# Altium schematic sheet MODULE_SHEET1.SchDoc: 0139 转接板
size 1188 x 840 mm; REV: 1.0; DESIGNER: LouKangHua
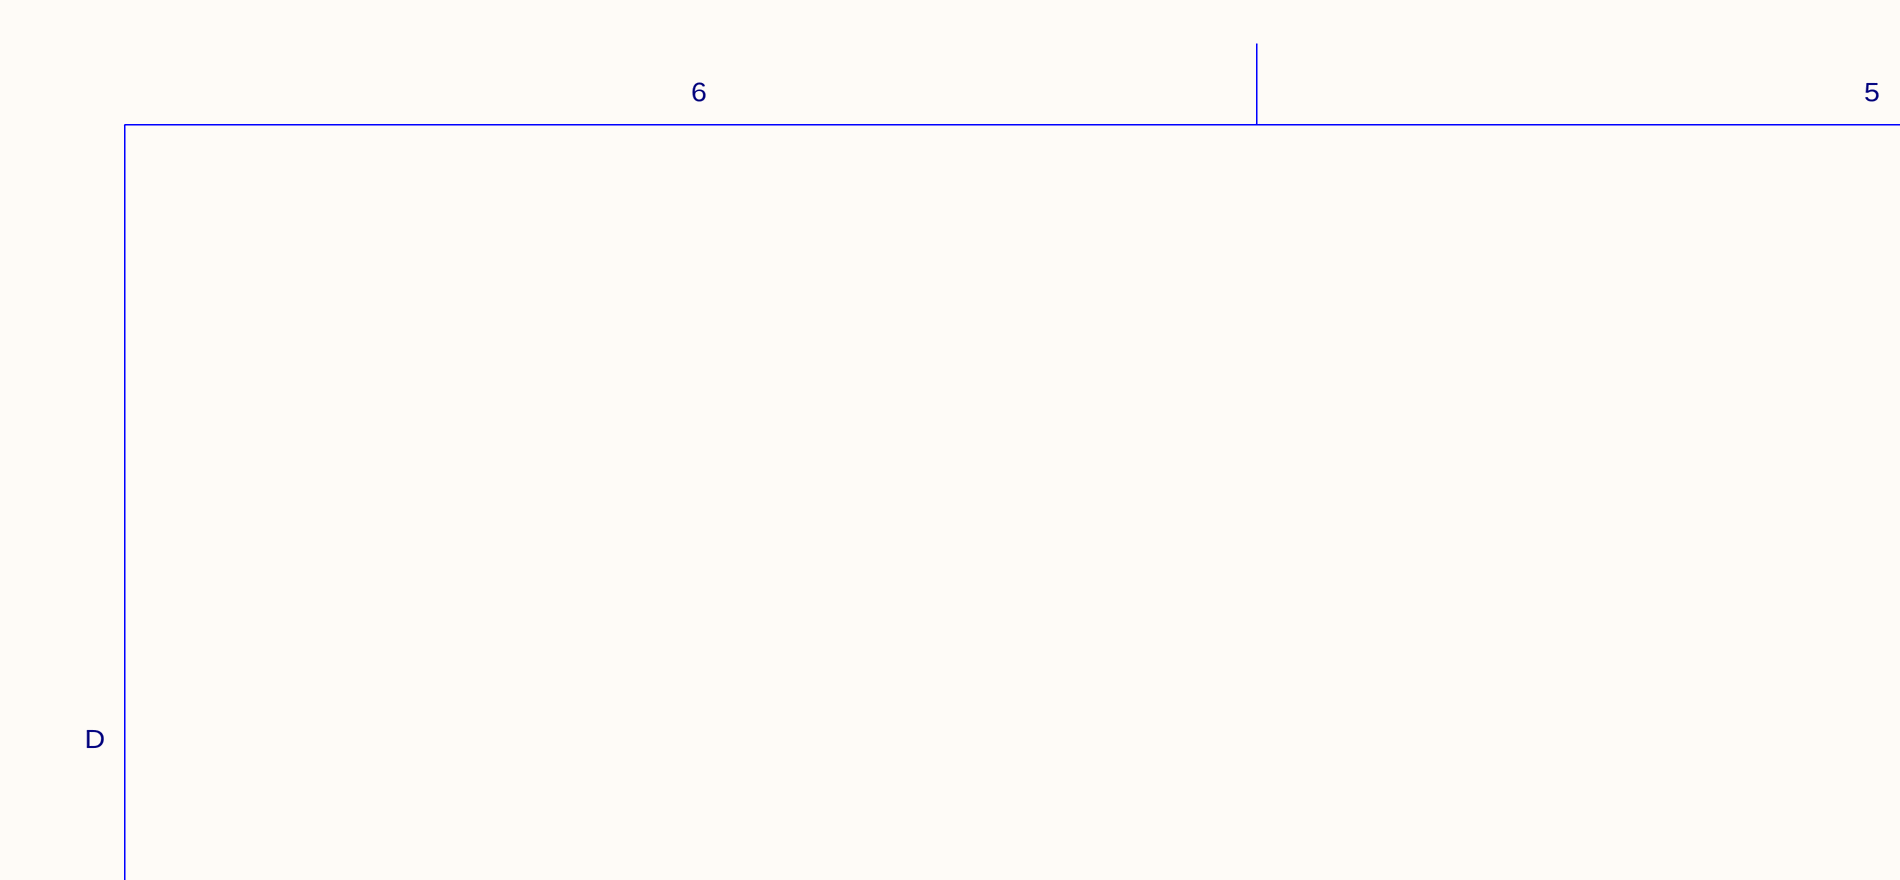
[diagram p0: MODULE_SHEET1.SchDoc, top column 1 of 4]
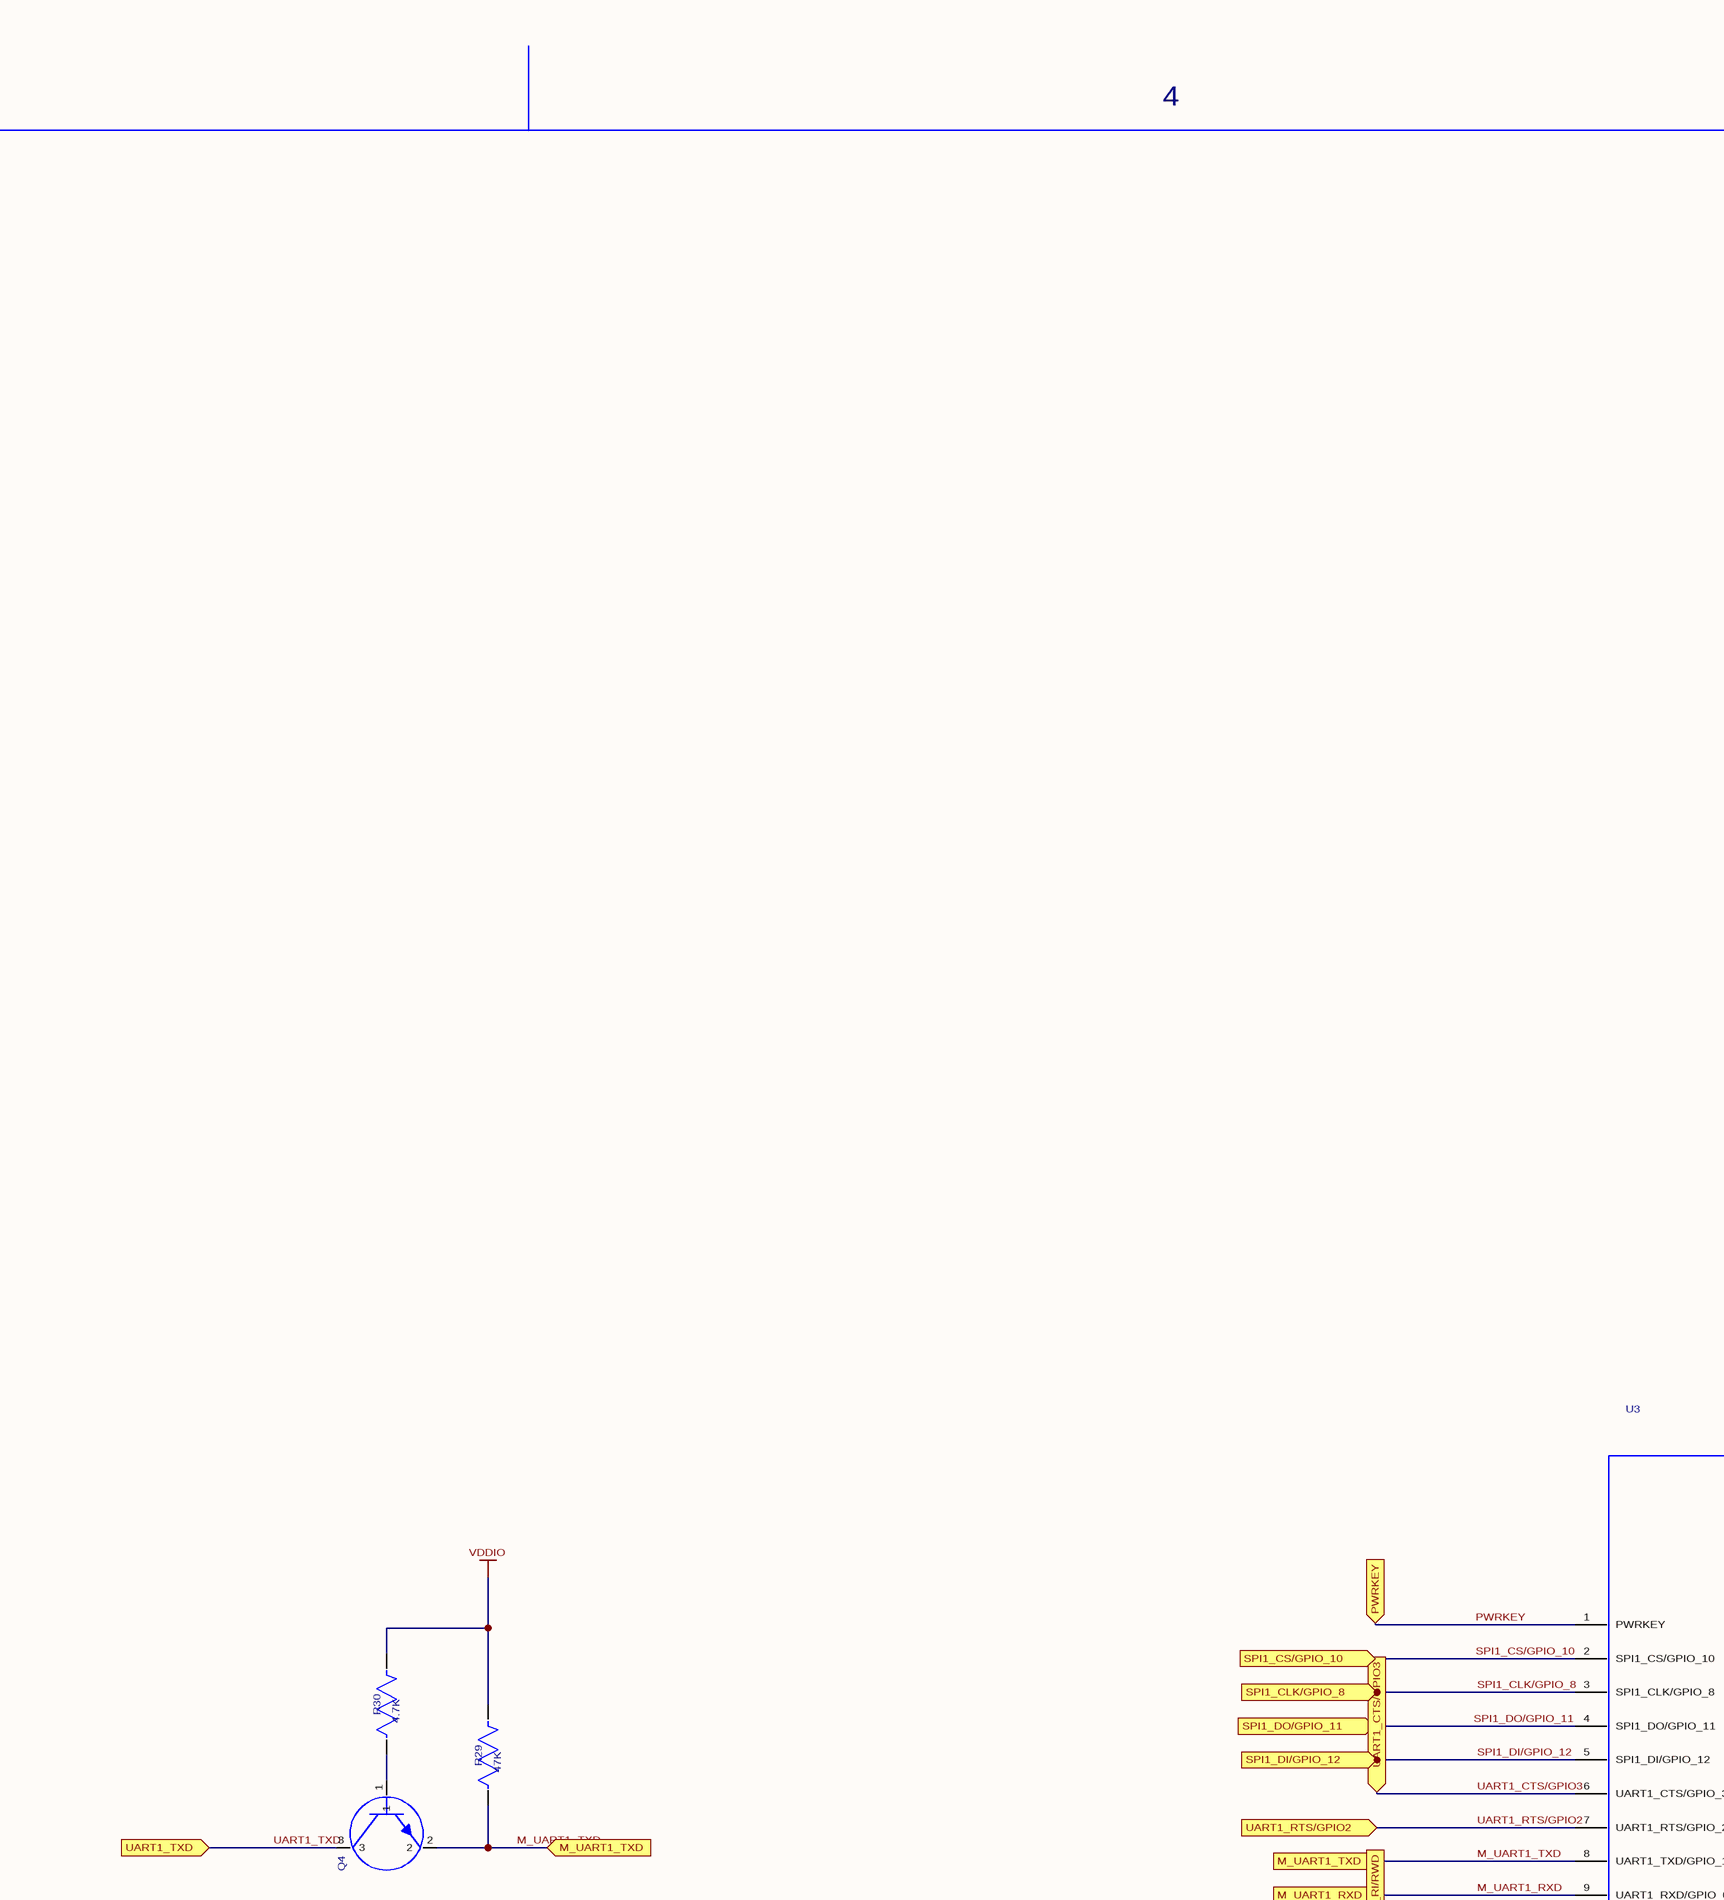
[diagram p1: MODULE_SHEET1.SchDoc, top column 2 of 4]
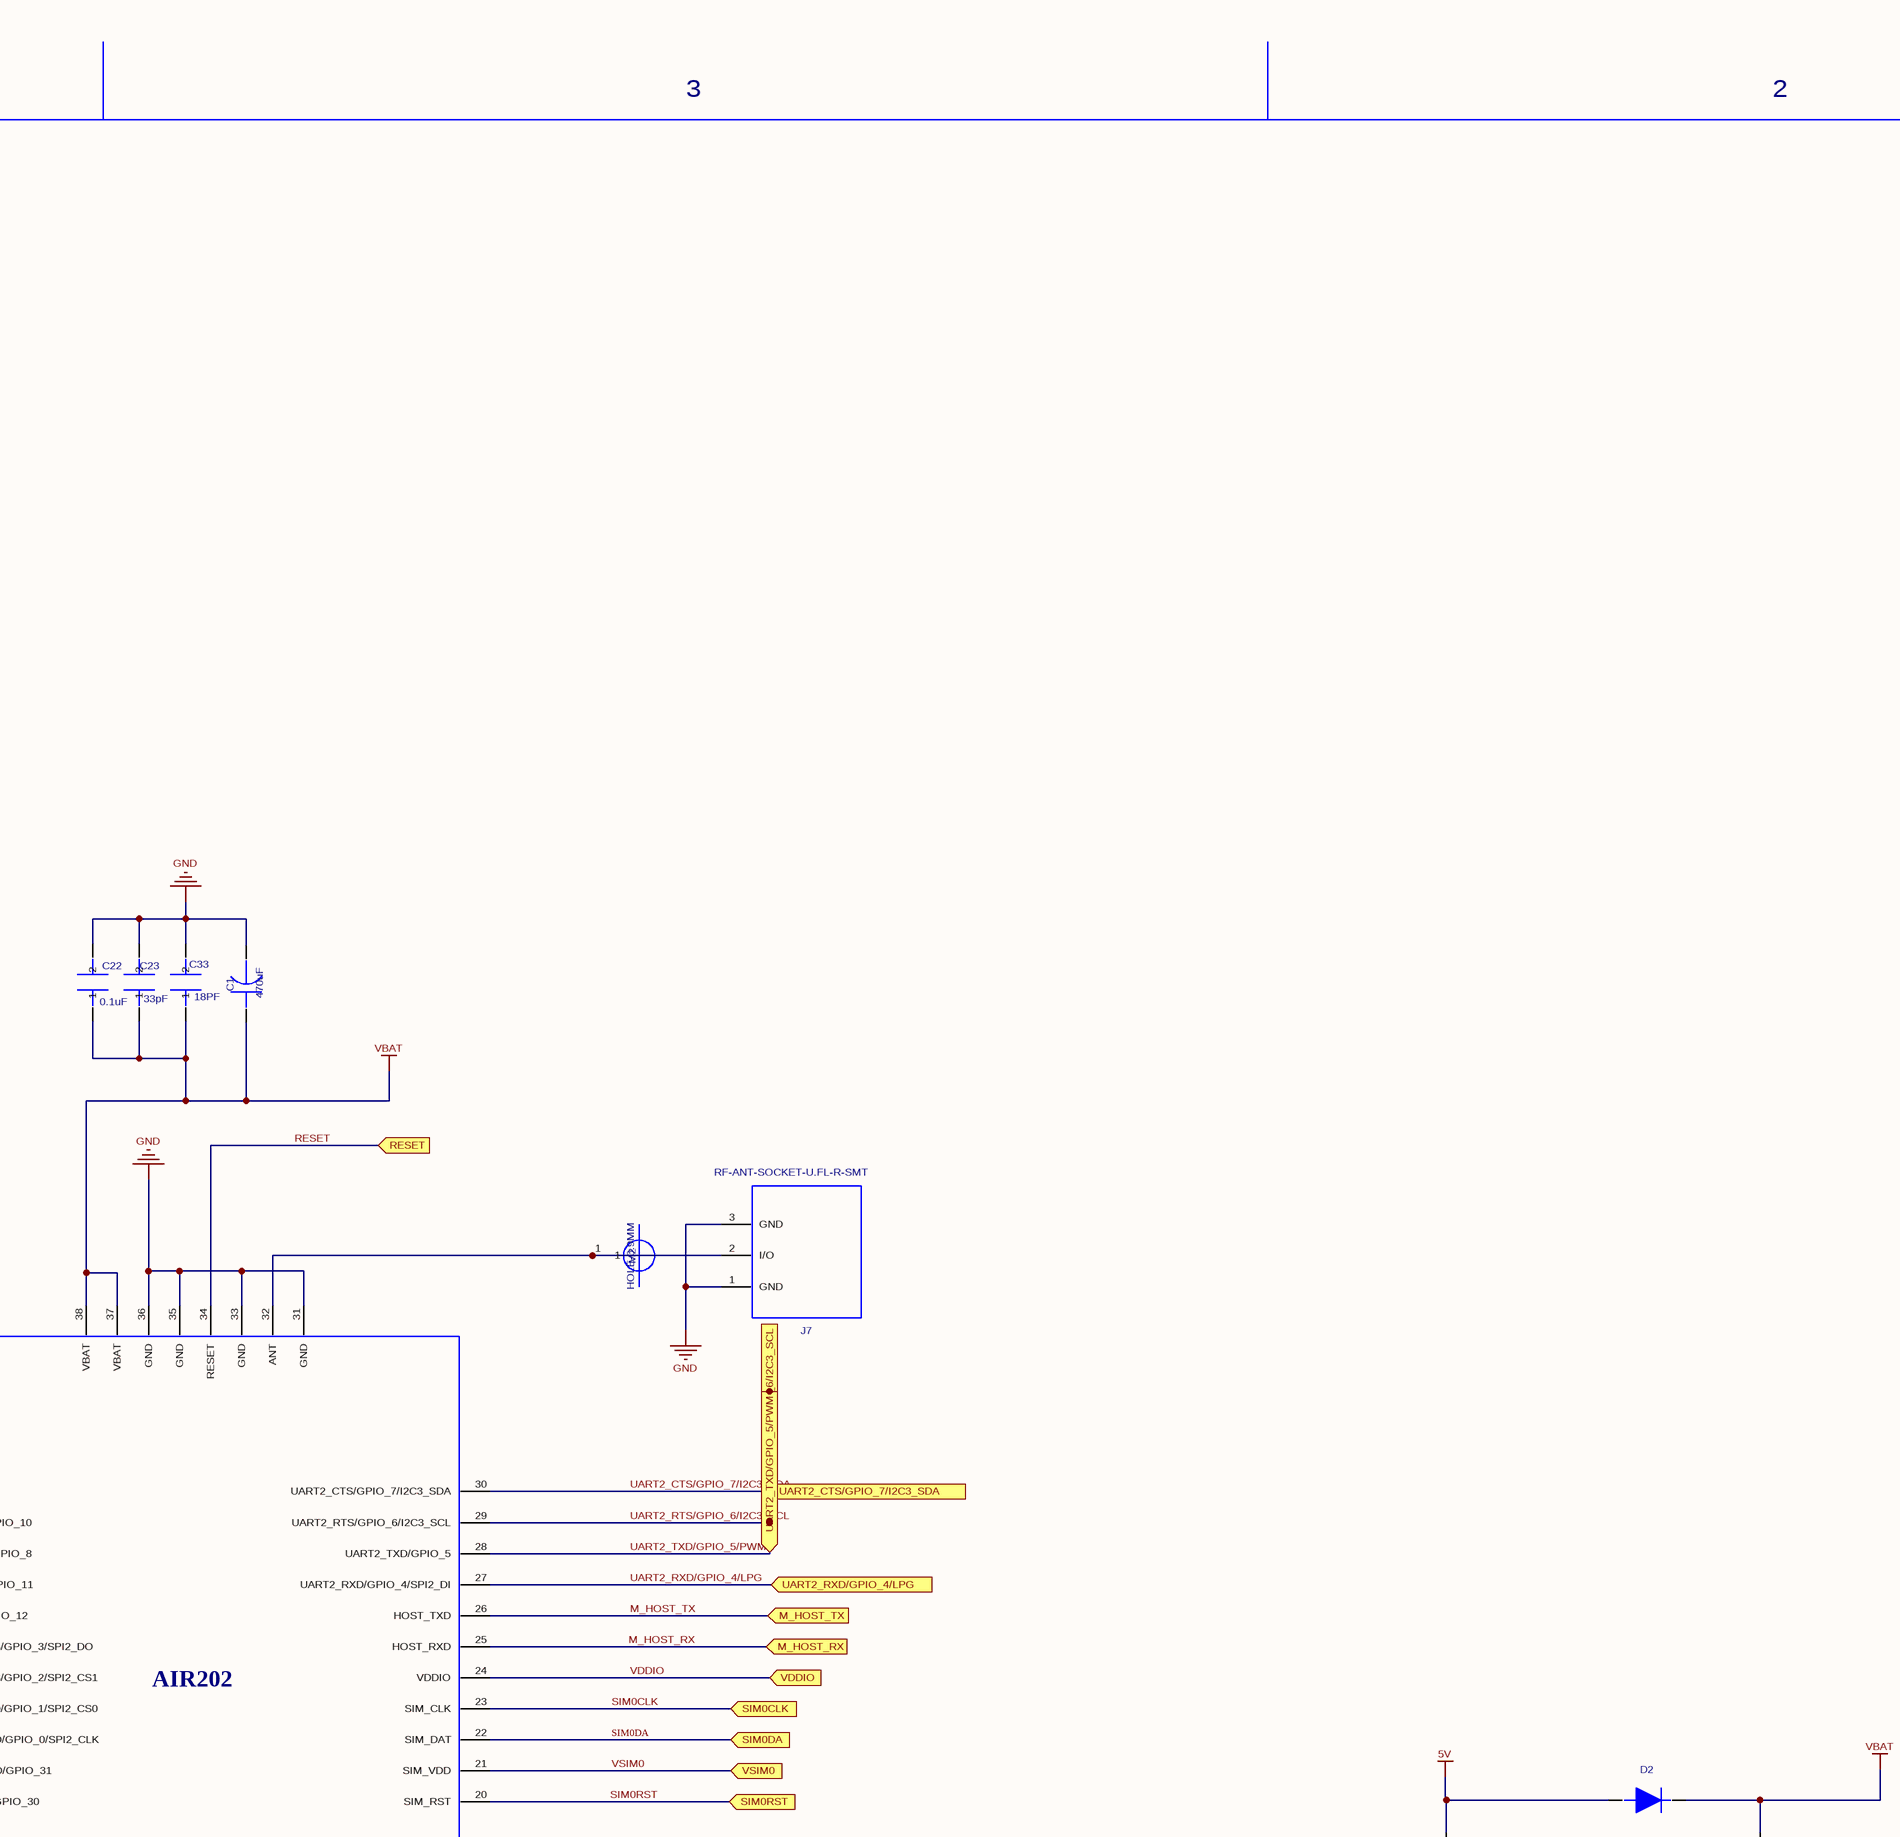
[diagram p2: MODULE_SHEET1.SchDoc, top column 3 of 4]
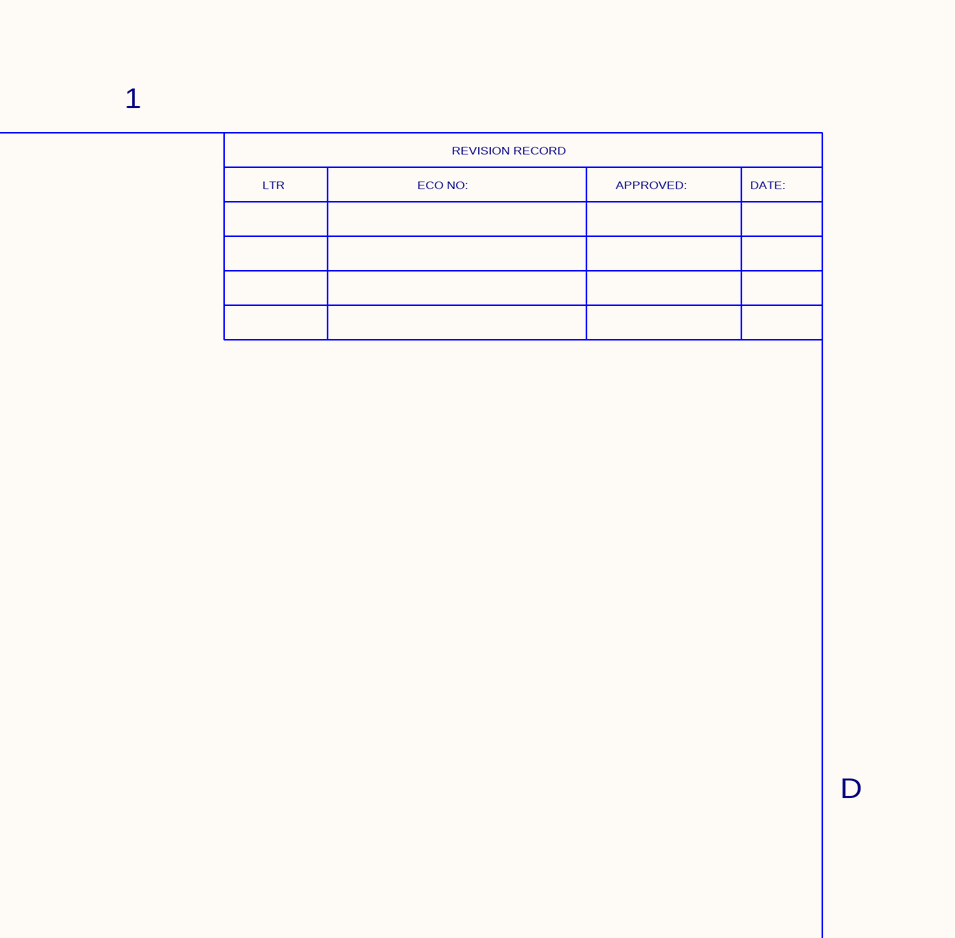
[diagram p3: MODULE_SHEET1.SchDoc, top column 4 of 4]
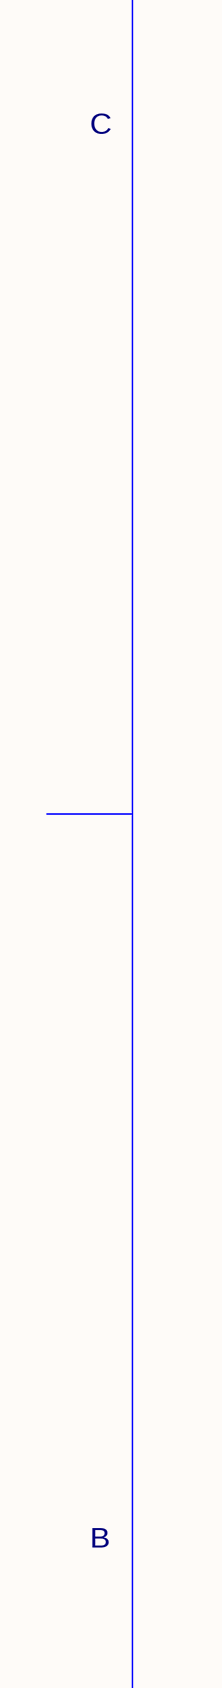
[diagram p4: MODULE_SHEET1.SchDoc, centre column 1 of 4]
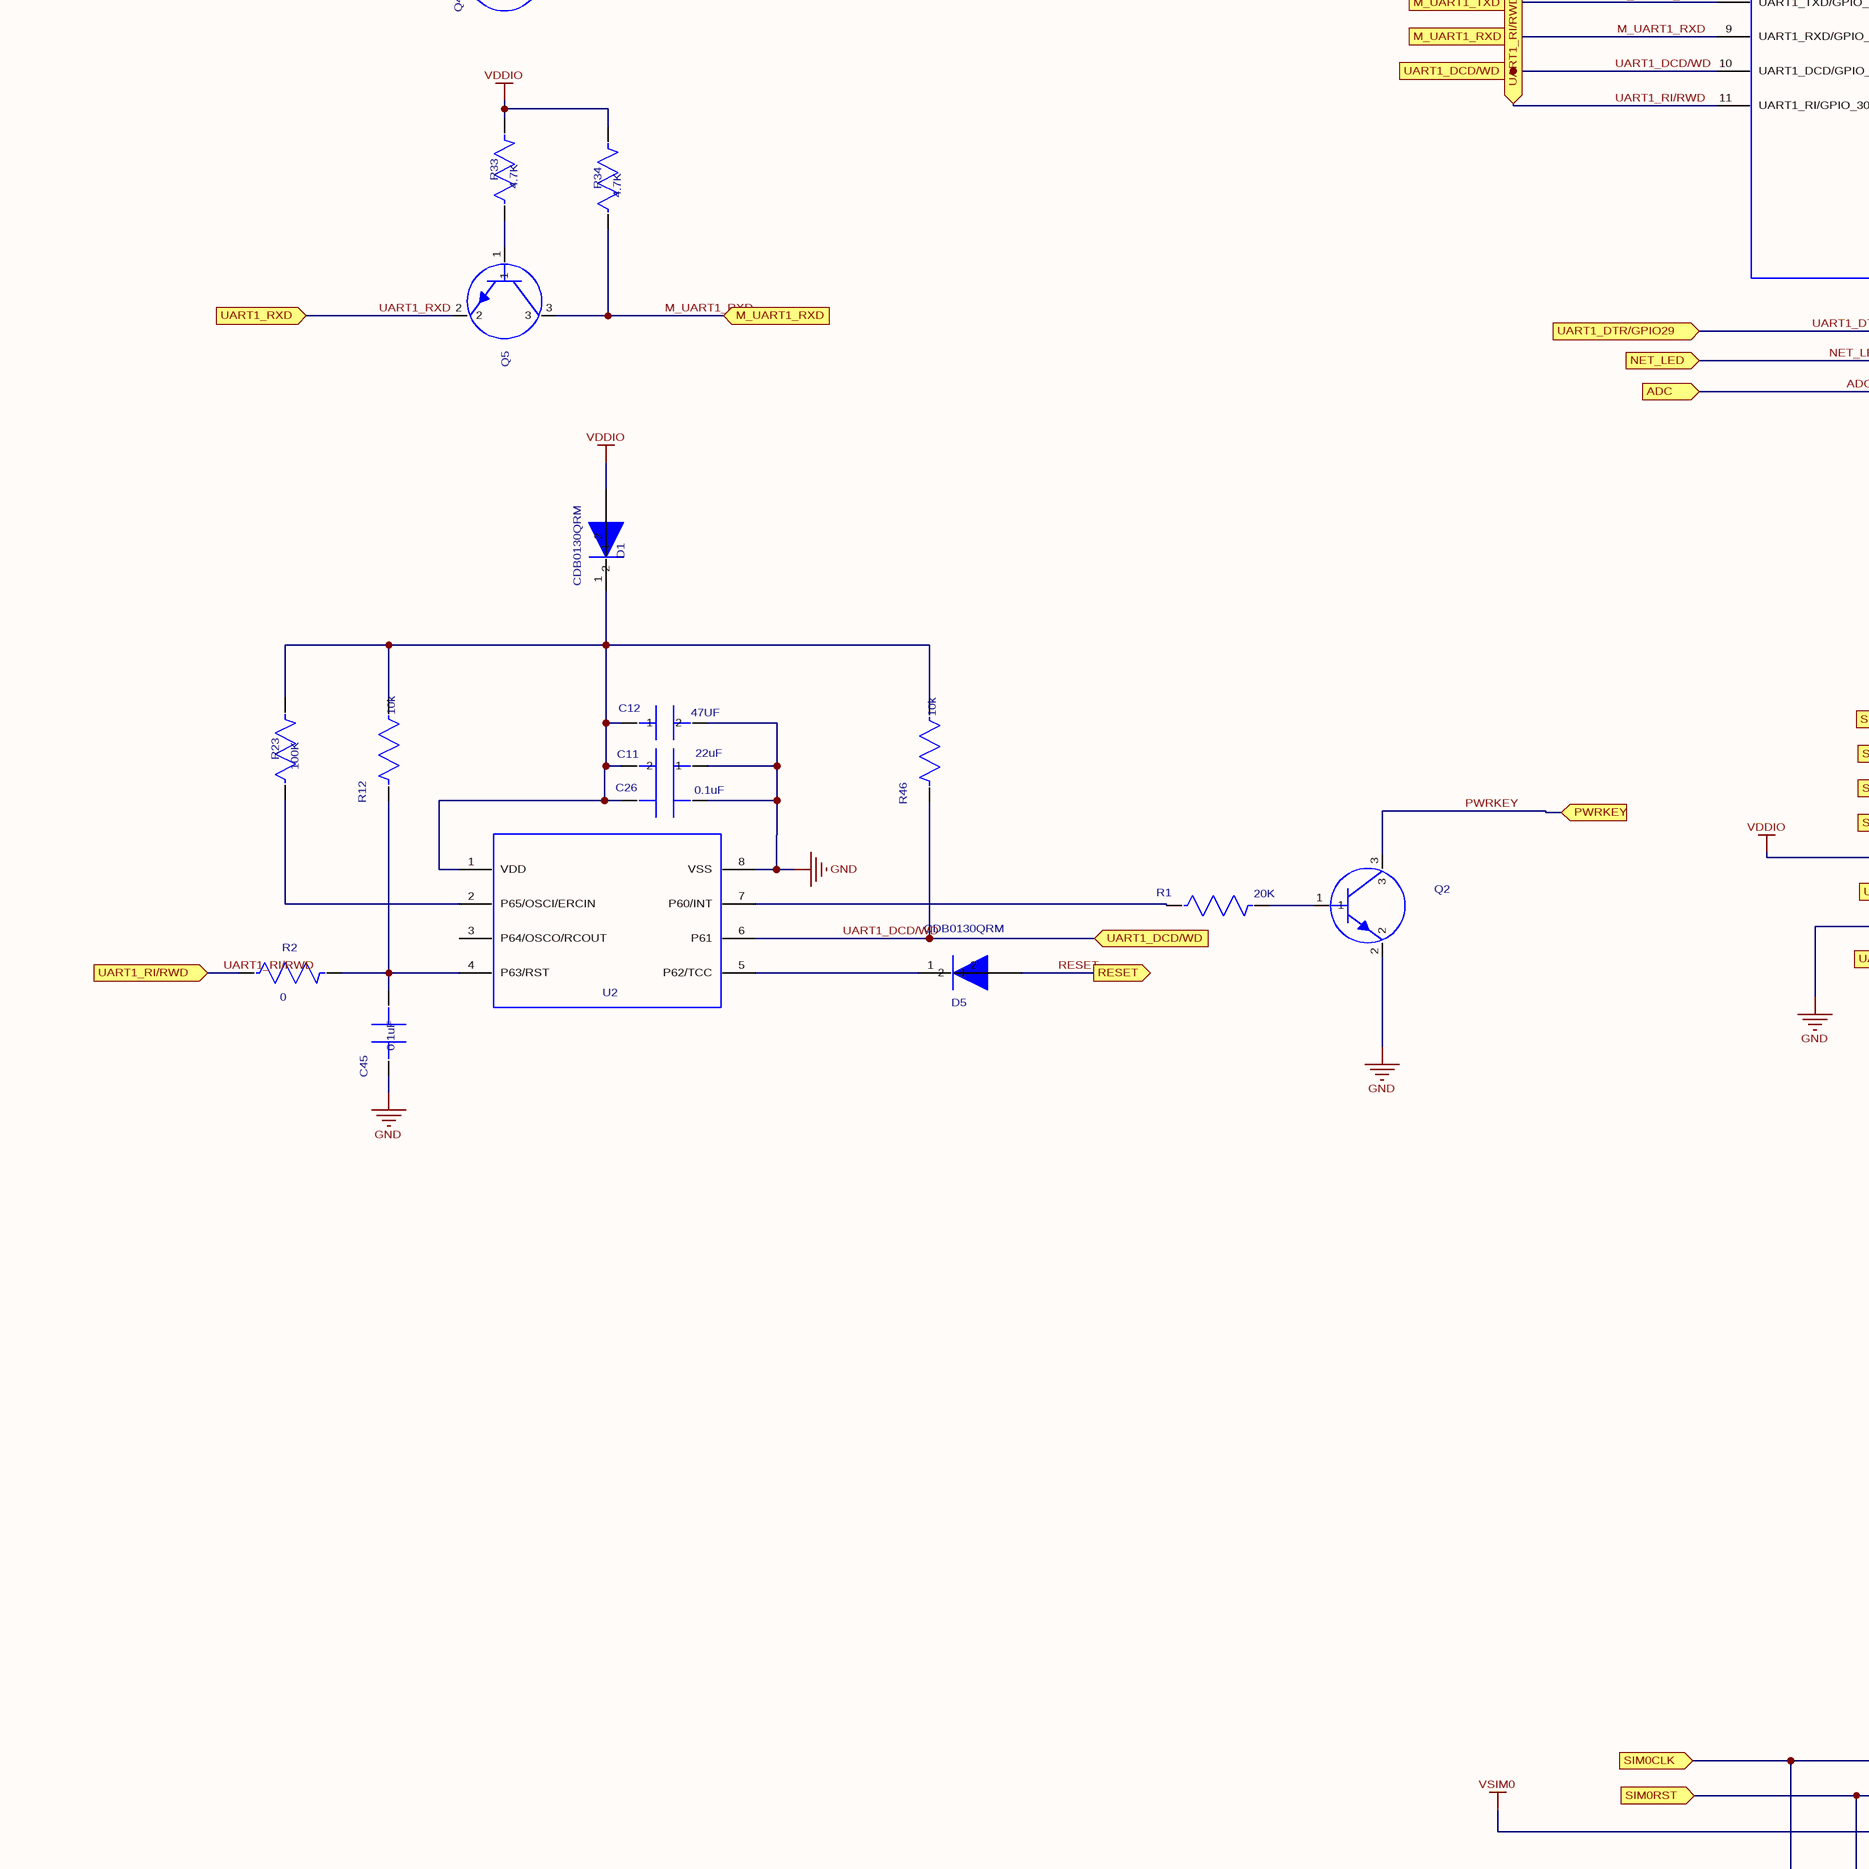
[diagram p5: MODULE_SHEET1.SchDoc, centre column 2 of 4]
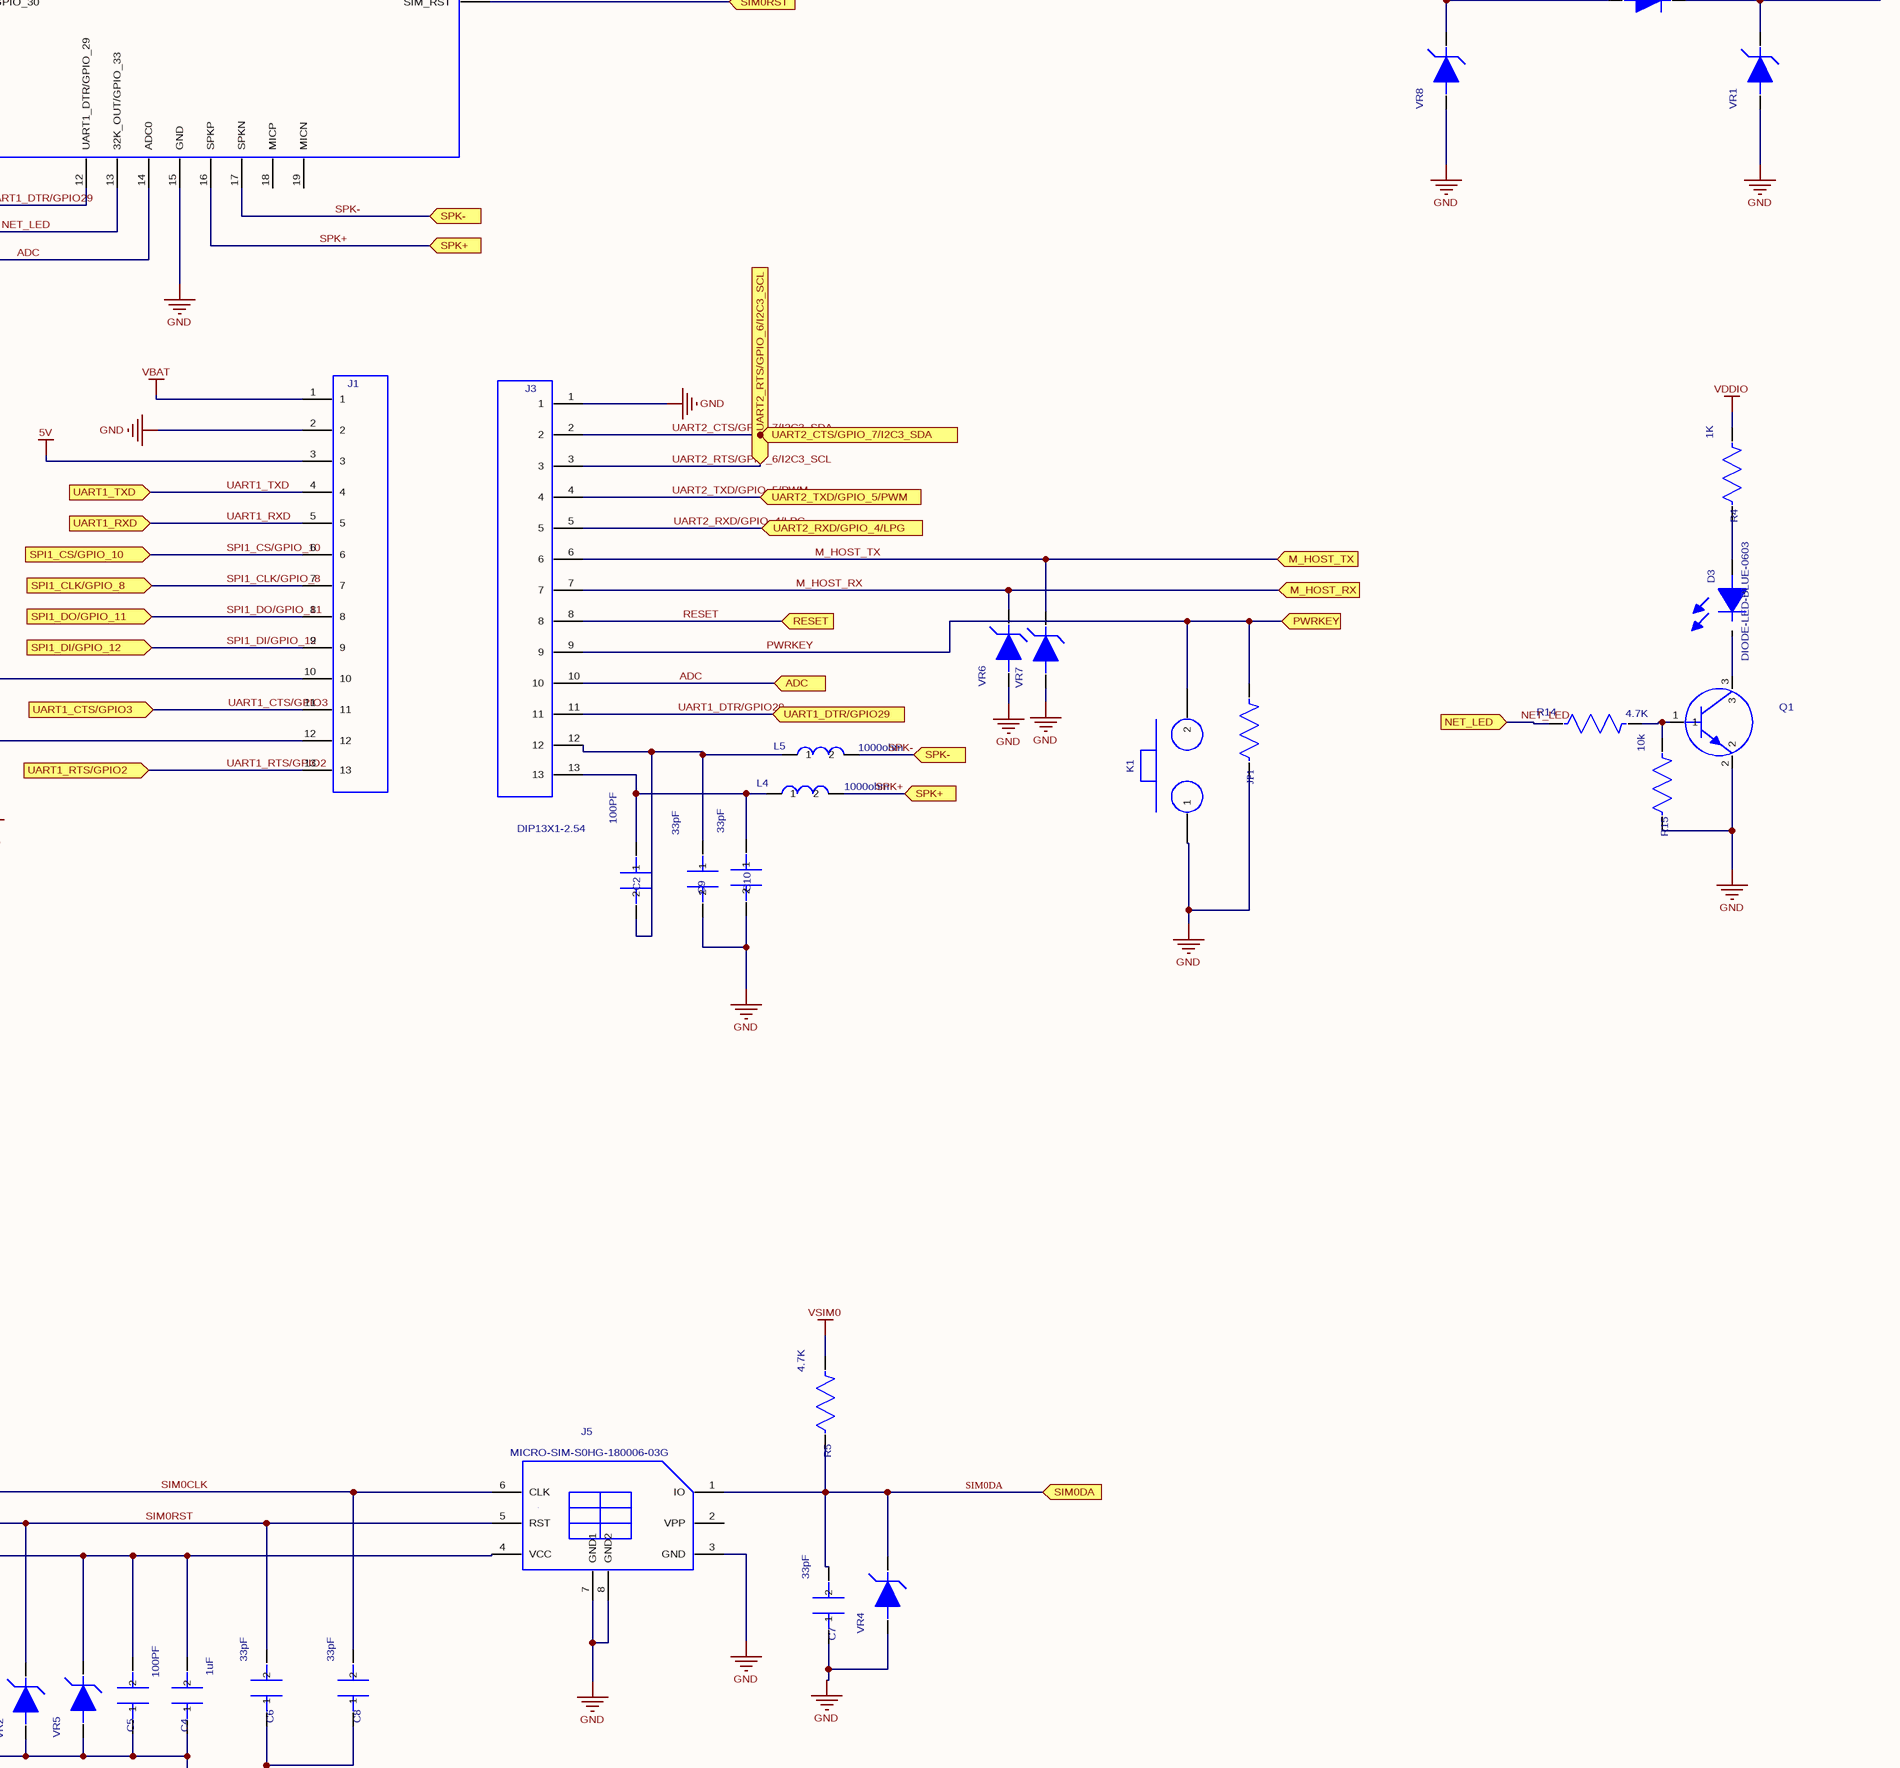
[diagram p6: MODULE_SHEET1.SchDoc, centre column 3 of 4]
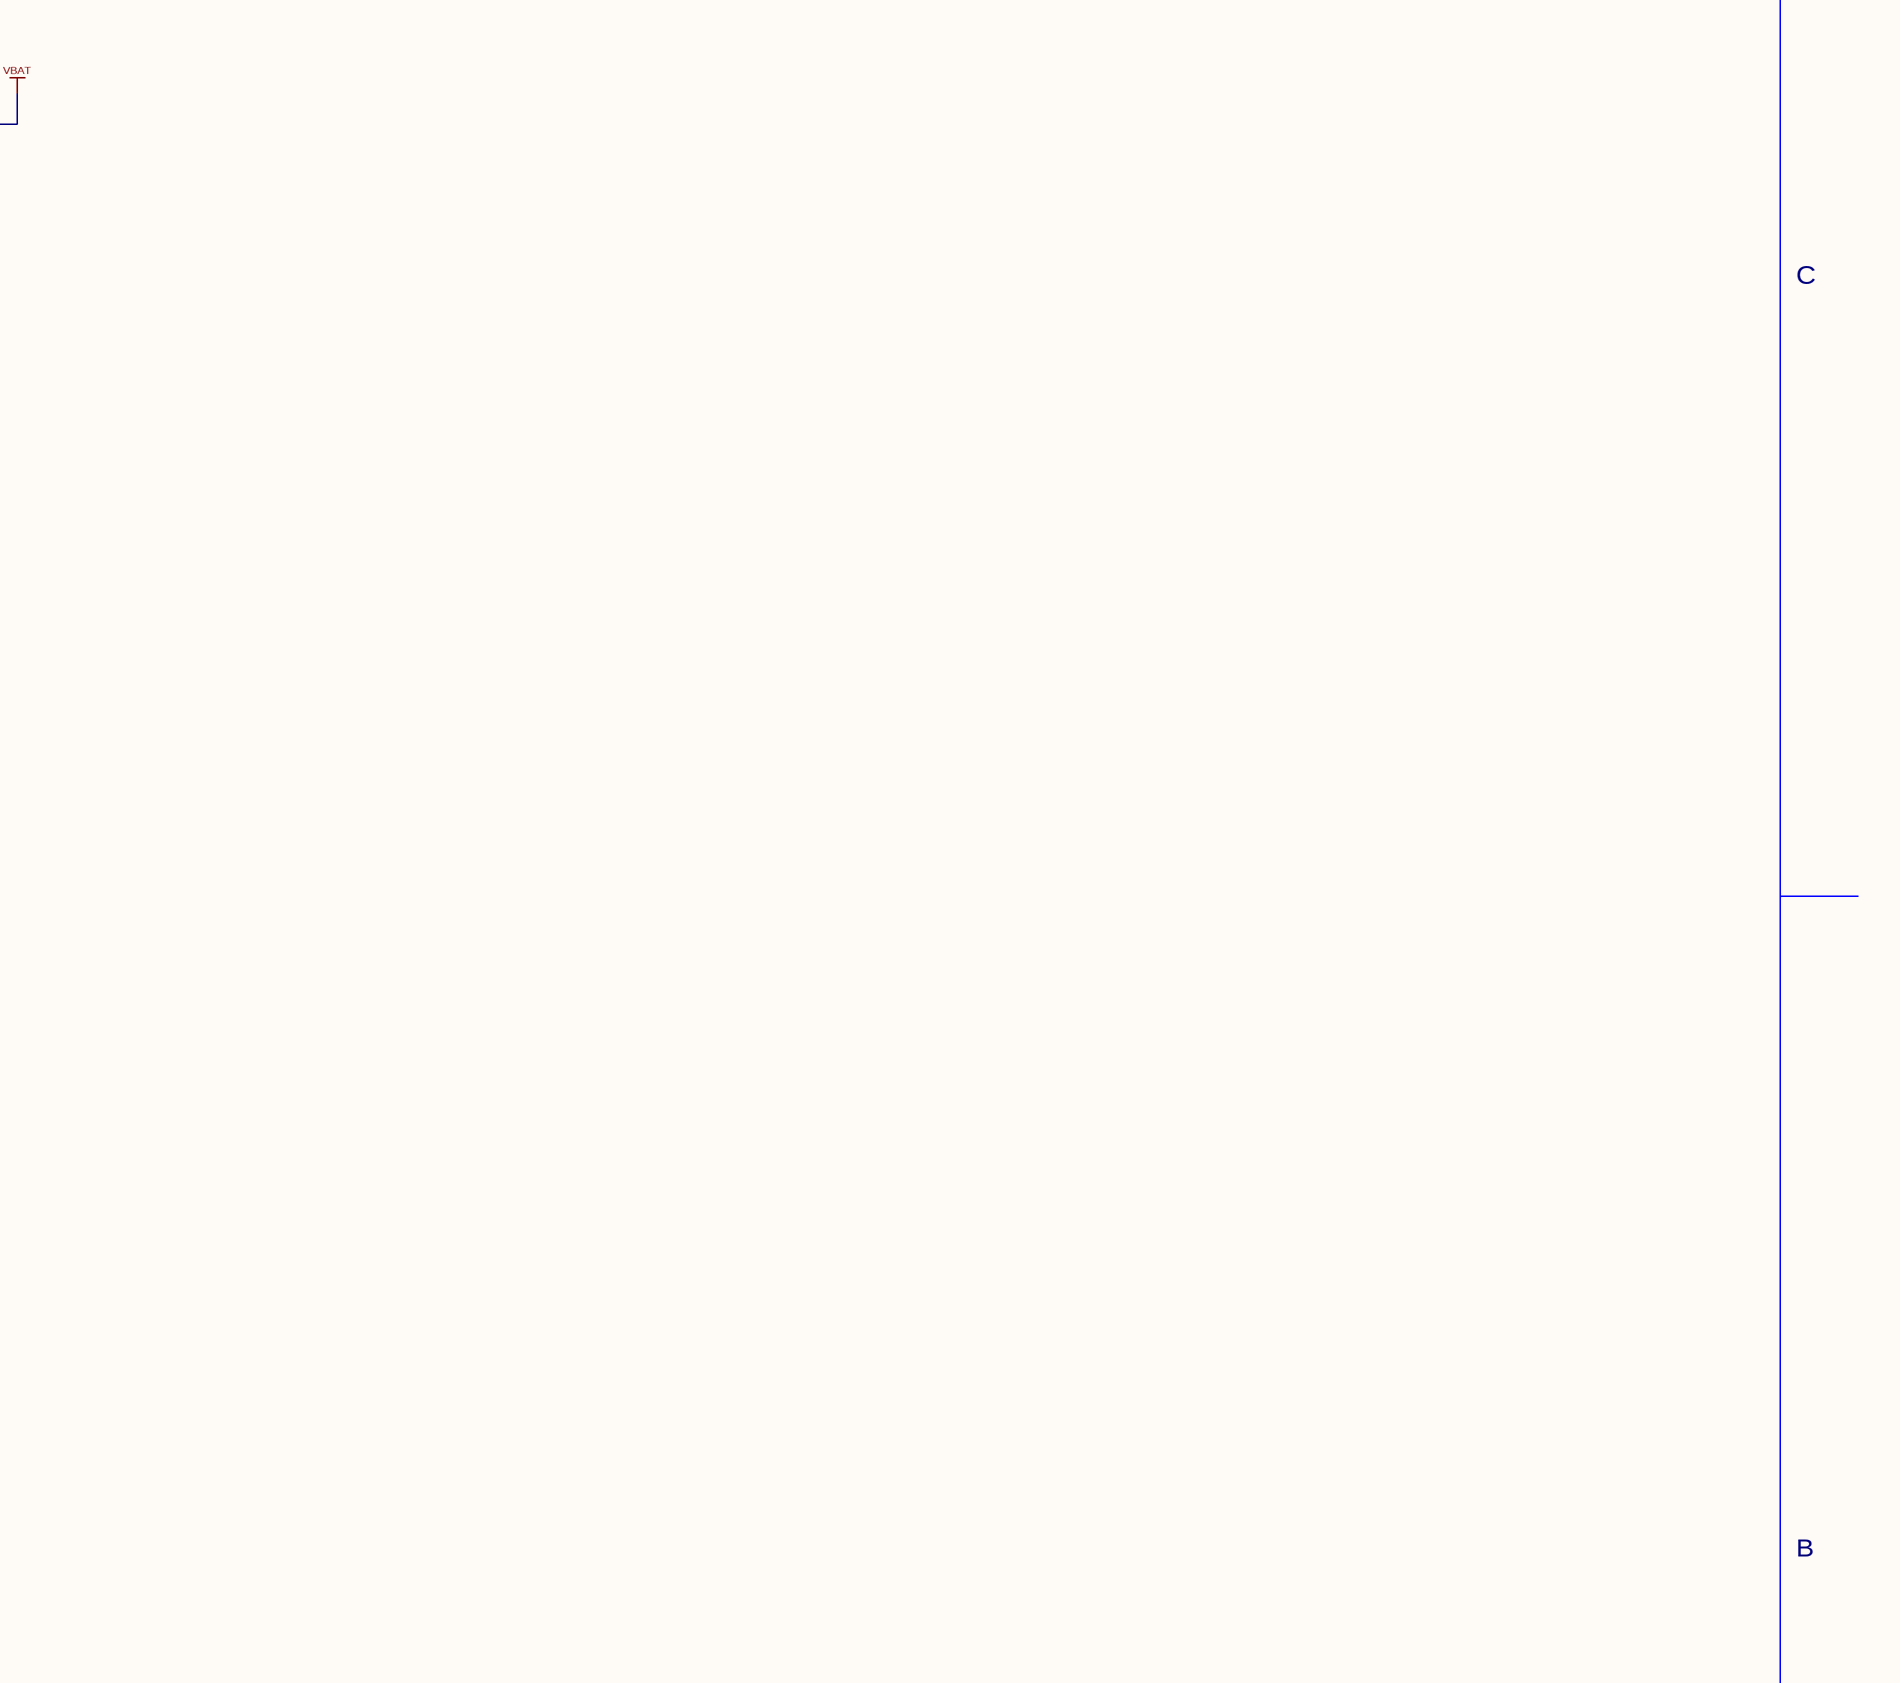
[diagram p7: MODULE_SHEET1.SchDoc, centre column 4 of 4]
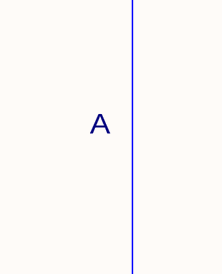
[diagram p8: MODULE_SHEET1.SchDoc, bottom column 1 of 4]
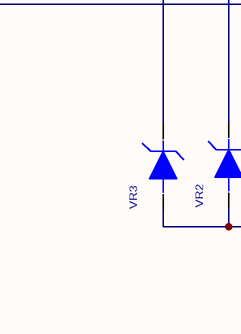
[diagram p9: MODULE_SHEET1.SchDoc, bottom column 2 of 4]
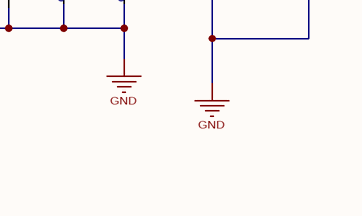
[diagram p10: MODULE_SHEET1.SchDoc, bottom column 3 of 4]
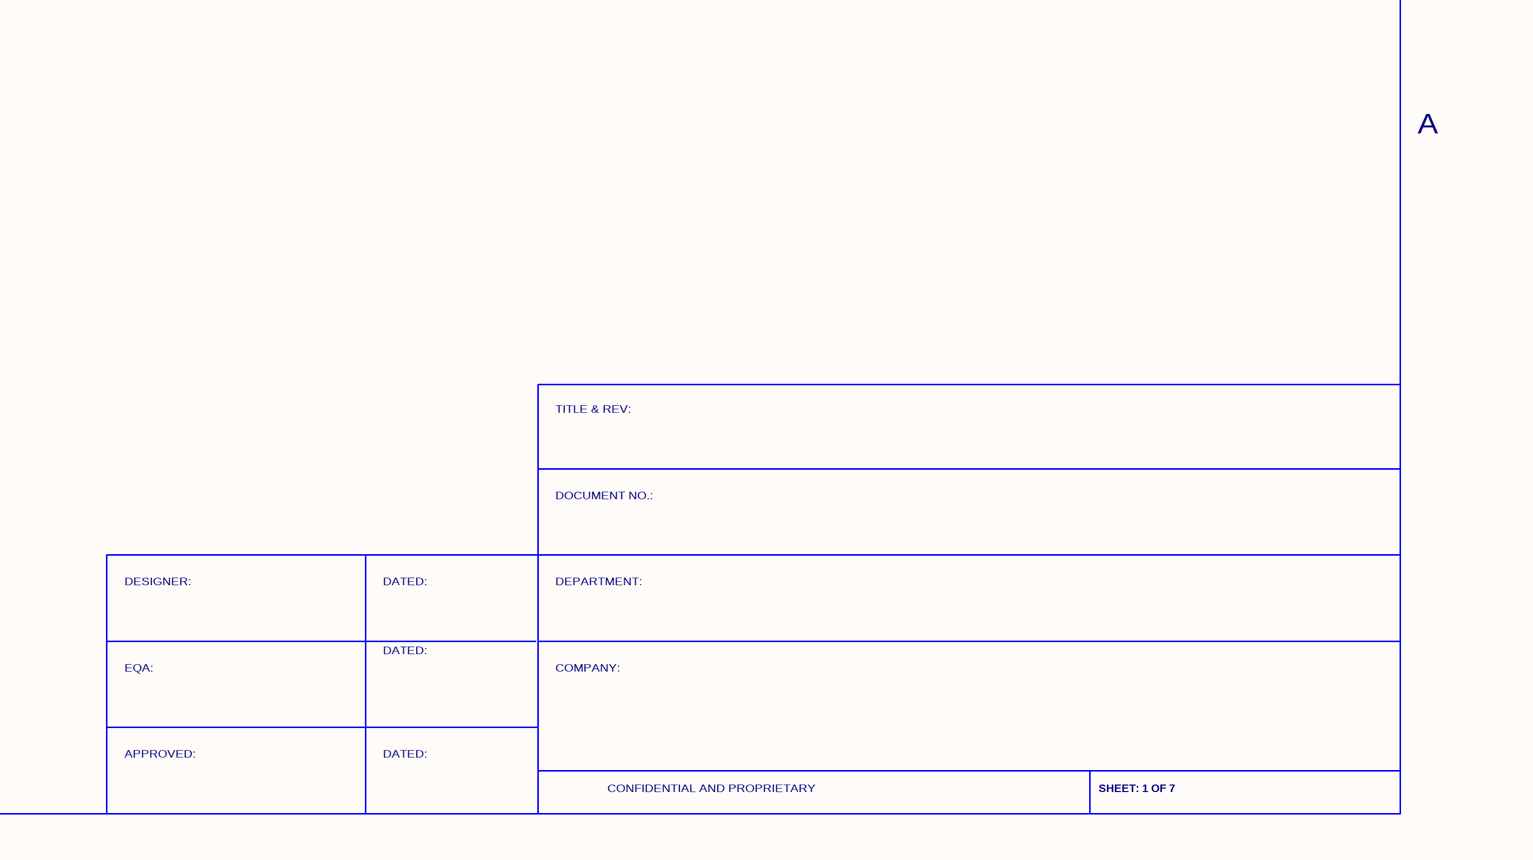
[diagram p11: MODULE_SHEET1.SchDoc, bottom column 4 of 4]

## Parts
C1  value 470uF  [CASEN]  (hidden comment: CAP-TAN-100UF-CASEN)
C2  value 100PF  [SC0402]  (hidden comment: CAP-100PF-0402-C0G)
C4  value 1uF  [SC0402]  (hidden comment: CAP-1UF-0402-X5R)
C5  value 100PF  [SC0402]  (hidden comment: CAP-100PF-0402-C0G)
C6  value 33pF  [SC0402]  (hidden comment: CAP-33PF-0402-C0G)
C7  value 33pF  [SC0402]  (hidden comment: CAP-33PF-0402-C0G)
C8  value 33pF  [SC0402]  (hidden comment: CAP-33PF-0402-C0G)
C9  value 33pF  [SC0402]  (hidden comment: CAP-33PF-0402-C0G)
C10  value 33pF  [SC0402]  (hidden comment: CAP-33PF-0402-C0G)
C11  value 22uF  [SC0603]  (hidden comment: CAP-4.7UF-0603-X5R)
C12  value 47UF  [SC1206]  (hidden comment: CAP-47UF-1206-X5R)
C22  value 0.1uF  [SC0402]  (hidden comment: CAP-0.1UF-0402-X7R)
C23  value 33pF  [SC0402]  (hidden comment: CAP-33PF-0402-C0G)
C26  value 0.1uF  [SC0402]  (hidden comment: CAP-0.1UF-0402-X5R-10V)
C33  value 18PF  [SC0402]  (hidden comment: CAP-18PF-0402-C0G)
C45  value 0.1uF  [SC0402]  (hidden comment: CAP-0.1UF-0402-X5R-10V)
D1  CDB0130QRM  [ESD-TVS-UM5079]
D2  SS14  [DO-214AC]  (value not drawn)
D3  DIODE-LED-BLUE-0603  [LED-0603]
D5  CDB0130QRM  [ESD-TVS-UM5079]
J1  DIP13X1-2.54  [DIP13X1-2.54]  (value not drawn)
J3  DIP13X1-2.54  [DIP13X1-2.54]
J5  MICRO-SIM-S0HG-180006-03G  [S0HG-180006-03G]
J7  RF-ANT-SOCKET-U.FL-R-SMT  [RF-ANT-SOCKET-U.FL-R-SMT]
JP1  RESISTANCE  [R60L08]  (value not drawn)
K1  KEY-2PIN  [KEY-2PIN]  (value not drawn)
L4  value 1000ohm  [SL0402]  (hidden comment: BEAD-1000OHM-0402)
L5  value 1000ohm  [SL0402]  (hidden comment: BEAD-1000OHM-0402)
M2  HOLE-0.9MM  [HOLE-0.9MM]
Q1  TRIODE-NPN-MMBT3904  [SOT-23(MMBT3904)]  (value not drawn)
Q2  TRIODE-NPN-MMBT3904  [SOT-23(MMBT3904)]  (value not drawn)
Q4  TRIODE-NPN-MMBT3904  [SOT-23(MMBT3904)]  (value not drawn)
Q5  TRIODE-NPN-MMBT3904  [SOT-23(MMBT3904)]  (value not drawn)
R1  value 20K  [SR0402]  (hidden comment: RES-20K-+/-5%-0402)
R2  value 0  [SR0402]  (hidden comment: RES-0-0402)
R4  value 1K  [SR0402]  (hidden comment: RES-1K-0402)
R5  value 4.7K  [SR0402]  (hidden comment: RES-4.7K-0402)
R12  value 10k  [SR0402]  (hidden comment: RES-10K-0402)
R14  value 4.7K  [SR0402]  (hidden comment: RES-4.7K-0402)
R15  value 10k  [SR0402]  (hidden comment: RES-10K-0402)
R23  value 100K  [SR0402]  (hidden comment: RES-100K-0402)
R29  value 47K  [SR0402]  (hidden comment: RES-47K-0402)
R30  value 4.7K  [SR0402]  (hidden comment: RES-4.7K-0402)
R33  value 4.7K  [SR0402]  (hidden comment: RES-4.7K-0402)
R34  value 4.7K  [SR0402]  (hidden comment: RES-4.7K-0402)
R46  value 10k  [SR0402]  (hidden comment: RES-10K-0402)
U2  EM78P153B-SOP8  [EM78P153B-SOP8]  (value not drawn)
U3  AIR202  [A6391_A11]
VR1  ESD-TVS-UM5079  [ESD-TVS-UM5079]  (value not drawn)
VR2  ESD-TVS-UM5079  [ESD-TVS-UM5079]  (value not drawn)
VR3  ESD-TVS-UM5079  [ESD-TVS-UM5079]  (value not drawn)
VR4  ESD-TVS-UM5079  [ESD-TVS-UM5079]  (value not drawn)
VR5  ESD-TVS-UM5079  [ESD-TVS-UM5079]  (value not drawn)
VR6  ESD-TVS-UM5079  [ESD-TVS-UM5079]  (value not drawn)
VR7  ESD-TVS-UM5079  [ESD-TVS-UM5079]  (value not drawn)
VR8  ESD-TVS-UM5079  [ESD-TVS-UM5079]  (value not drawn)

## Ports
ADC, M_HOST_RX, M_HOST_TX, M_UART1_RXD, M_UART1_TXD, NET_LED, PWRKEY, RESET, RESET (out), SIM0CLK, SIM0DA, SIM0RST, SPI1_CLK/GPIO_8, SPI1_CS/GPIO_10, SPI1_DI/GPIO_12, SPI1_DO/GPIO_11, SPK+, SPK-, UART1_CTS/GPIO3, UART1_DCD/WD, UART1_DTR/GPIO29, UART1_RI/RWD, UART1_RTS/GPIO2, UART1_RXD, UART1_TXD, UART2_CTS/GPIO_7/I2C3_SDA, UART2_RTS/GPIO_6/I2C3_SCL, UART2_RXD/GPIO_4/LPG, UART2_TXD/GPIO_5/PWM, VDDIO, VSIM0

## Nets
5V: D2.A J1.3 VR8.1
GND: C1.2 C4.1 C5.1 C6.1 C7.1 C8.1 C9.2 C10.2 C11.1 C12.2 C22.2 C23.2 C26.2 C33.2 C45.1 J1.2 J1.12 J3.1 J5.3(GND) J5.7(GND1) J5.8(GND2) J7.1(GND) J7.3(GND) JP1.1 K1.1 Q1.2 Q2.2 R15.1 U2.8(VSS) U3.15(GND) U3.31(GND) U3.33(GND) U3.35(GND) U3.36(GND) U3.39(GND) U3.40(GND) U3.41(GND) VR1.2 VR2.2 VR3.2 VR4.2 VR5.2 VR6.2 VR7.2 VR8.2
VBAT: C1.1 C22.1 C23.1 C33.1 D2.K J1.1 U3.37(VBAT) U3.38(VBAT) VR1.1
VDDIO: D1.2 J1.10 R4.2 R29.2 R30.2 R33.2 R34.2 U3.24(VDDIO) ; port VDDIO
VSIM0: C4.2 C5.2 J5.4(VCC) R5.2 U3.21(SIM_VDD) VR5.1 ; port VSIM0
ADC: J3.10 U3.14(ADC0) ; port ADC
M_HOST_RX: J3.7 U3.25(HOST_RXD) VR6.1 ; port M_HOST_RX
M_HOST_TX: J3.6 U3.26(HOST_TXD) VR7.1 ; port M_HOST_TX
M_UART1_RXD: Q5.3 R34.1 U3.9(UART1_RXD/GPIO_0/SPI2_CLK) ; port M_UART1_RXD
M_UART1_TXD: Q4.2 R29.1 U3.8(UART1_TXD/GPIO_1/SPI2_CS0) ; port M_UART1_TXD
NET_LED: R14.1 U3.13(32K_OUT/GPIO_33) ; port NET_LED
PWRKEY: J3.9 JP1.2 K1.2 Q2.3 U3.1(PWRKEY) ; port PWRKEY
RESET: D5.2 J3.8 U3.34(RESET) ; port RESET
SIM0CLK: C8.2 J5.6(CLK) U3.23(SIM_CLK) VR3.1 ; port SIM0CLK
SIM0DA: C7.2 J5.1(IO) R5.1 U3.22(SIM_DAT) VR4.1 ; port SIM0DA
SIM0RST: C6.2 J5.5(RST) U3.20(SIM_RST) VR2.1 ; port SIM0RST
SPI1_CLK/GPIO_8: J1.7 U3.3(SPI1_CLK/GPIO_8) ; port SPI1_CLK/GPIO_8
SPI1_CS/GPIO_10: J1.6 U3.2(SPI1_CS/GPIO_10) ; port SPI1_CS/GPIO_10
SPI1_DI/GPIO_12: J1.9 U3.5(SPI1_DI/GPIO_12) ; port SPI1_DI/GPIO_12
SPI1_DO/GPIO_11: J1.8 U3.4(SPI1_DO/GPIO_11) ; port SPI1_DO/GPIO_11
SPK+: L4.2 U3.16(SPKP) ; port SPK+
SPK-: L5.2 U3.17(SPKN) ; port SPK-
UART1_CTS/GPIO3: J1.11 U3.6(UART1_CTS/GPIO_3/SPI2_DO) ; port UART1_CTS/GPIO3
UART1_DCD/WD: R46.2 U2.6(P61) U3.10(UART1_DCD/GPIO_31) ; port UART1_DCD/WD
UART1_DTR/GPIO29: J3.11 U3.12(UART1_DTR/GPIO_29) ; port UART1_DTR/GPIO29
UART1_RI/RWD: R2.1 U3.11(UART1_RI/GPIO_30) ; port UART1_RI/RWD
UART1_RTS/GPIO2: J1.13 U3.7(UART1_RTS/GPIO_2/SPI2_CS1) ; port UART1_RTS/GPIO2
UART1_RXD: J1.5 Q5.2 ; port UART1_RXD
UART1_TXD: J1.4 Q4.3 ; port UART1_TXD
UART2_CTS/GPIO_7/I2C3_SDA: J3.2 U3.30(UART2_CTS/GPIO_7/I2C3_SDA) ; port UART2_CTS/GPIO_7/I2C3_SDA
UART2_RTS/GPIO_6/I2C3_SCL: J3.3 U3.29(UART2_RTS/GPIO_6/I2C3_SCL) ; port UART2_RTS/GPIO_6/I2C3_SCL
UART2_RXD/GPIO_4/LPG: J3.5 U3.27(UART2_RXD/GPIO_4/SPI2_DI) ; port UART2_RXD/GPIO_4/LPG
UART2_TXD/GPIO_5/PWM: J3.4 U3.28(UART2_TXD/GPIO_5) ; port UART2_TXD/GPIO_5/PWM
NetC2_1: C2.1 C10.1 J3.13 L4.1
NetC2_2: C2.2 C9.1 J3.12 L5.1
NetC11_2: C11.2 C12.1 C26.1 D1.1 R12.1 R23.2 R46.1 U2.1(VDD)
NetC45_2: C45.2 R2.2 R12.2 U2.4(P63/RST)
NetD3_1: D3.1 R4.1
NetD3_2: D3.2 Q1.3
NetD5_1: D5.1 U2.5(P62/TCC)
NetJ7_2: J7.2(I/O) M2.1 U3.32(ANT)
NetQ1_1: Q1.1 R14.2 R15.2
NetQ2_1: Q2.1 R1.2
NetQ4_1: Q4.1 R30.1
NetQ5_1: Q5.1 R33.1
NetR1_1: R1.1 U2.7(P60/INT)
NetR23_1: R23.1 U2.2(P65/OSCI/ERCIN)

Not connected (* = marked no-connect by the designer): J5 2(VPP); U2 3(P64/OSCO/RCOUT); U3 18(MICP) 19(MICN)

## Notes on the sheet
- 6
- 5
- 4
- 3
- 2
- 1
- REVISION RECORD
- LTR
- ECO NO:
- APPROVED:
- DATE:
- D
- C
- B
- A
- TITLE & REV:
- DESIGNER:
- DATED:
- DOCUMENT NO.:
- DEPARTMENT:
- EQA:
- COMPANY:
- CONFIDENTIAL AND PROPRIETARY
- SHEET: 1 OF 7

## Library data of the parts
C1 = CAP-TAN-100UF-CASEN: CAP TAN;100uF;+/-20%;16V;CASEN;3.0mm;ROHS; Manufacture 1: Nichicon; Manufacture 1 P/N: F931C107MNC; Serial Number: 80230830001
C2 C5 = CAP-100PF-0402-C0G: CAP CER C0G;100PF;+/-5%;50V;0402;0.5mm;ROHS; Manufacture 1: MURATA;TDK;Yageo;Walsin;Eyang; Manufacture 1 P/N: GRM1555C1H101J****;C1005C0G1H101J;CC0402JRNP09BN101;0402N101J500CT;C0402C0G101J500N*; Geometry.Height: 0.55mm; Serial Number: 80214650002
C4 = CAP-1UF-0402-X5R: CAP CER X5R;1uF;+/-10%;6.3V;0402;0.5mm;ROHS; Manufacture 1 P/N: GRM155R60J105K****;CC0402KRX5R5BB105;C1005X5R0J105KT;JMK105BJ105KV-F;ECJ0EB0J105K;0402X105K6R3CT;CL05A105KQ5NNNC; Manufacture 1: Murata;Yageo;TDK;Taiyo Yuden;Panasonic;Walsin;Samsung; Serial Number: 80214710001; Geometry.Height: 0.55mm
C6-C10 C23 = CAP-33PF-0402-C0G: CAP CER C0G;33PF;+/-5%;50V;0402;0.5mm;ROHS; Manufacture 1: MURATA;Yageo;Eyang; Manufacture 1 P/N: GRM1555C1H330J****;CC0402JRNPO9BN330;C0402C0G330J500N*; Geometry.Height: 0.55mm; Serial Number: 80214650008
C11 = CAP-4.7UF-0603-X5R: CAP CER X5R;4.7uF;+/-10%;6.3V;0603;0.8mm;ROHS; Manufacture 1: Murata;TDK;Yageo;Taiyo Yuden;Panasonic;Kyocera;Samsung;; Manufacture 1 P/N: GRM188R60J475K****;C1608X5R0J475K;CC0603KRX5R5BB475;JMK107BJ475KA-T;ECJ1VB0J475K;CV105X5R475K06ATCL10A475KQ8NNNC;; Geometry.Height: 0.95mm; Serial Number: 80216710002
C12 = CAP-47UF-1206-X5R: CAP CER X5R;47uF;±20%;6.3V;1206;1.8mm;ROHS; Manufacture 1: MURATA; Manufacture 1 P/N: GRM31CR60J476M****; Serial Number: 80211810001
C22 = CAP-0.1UF-0402-X7R: CAP CER X7R;0.1uF;+/-10%;16V;0402;0.5mm;ROHS; Manufacture 1: MURATA;Walsin;Yageo;Eyang;; Manufacture 1 P/N: GRM155R71C104K****;0402X104K160CT;CC0402KRX7R7BB104;C0402X5R104K160N*; Geometry.Height: 0.55mm; Serial Number: 80214730006
C26 C45 = CAP-0.1UF-0402-X5R-10V: CAP CER X5R/X7R;0.1uF;+/-10%;10V;0402;0.5mm;ROHS; Manufacture 1 P/N: GRM155R61A104K****;GRM155R71A104K****;CC0402KRX5R6BB104;0402X104K100CT;C0402X5R104K100N*; Manufacture 1: Murata;Yageo;Walsin;Eyang; Serial Number: 80214720001; Geometry.Height: 0.55mm
C33 = CAP-18PF-0402-C0G: CAP CER C0G;18PF;+/-5%;50V;0402;0.5mm;ROHS; Manufacture 1: MURATA;Yageo;Eyang; Manufacture 1 P/N: GRM1555C1H180J****;CC0402JRNPO9BN180;C0402C0G180J500N*; Geometry.Height: 0.55mm; Serial Number: 80214650006
D1 D5 = CDB0130QRM: Schottky Diode;20V;2.0A/0.5V;SMB;4.5*3.9*2.62mm;ROHS; Manufacture 1: Diodes; Manufacture 1 P/N: B220-13-F; Geometry.Height: 0.7mm; Serial Number: 81260000005
D2 = SS14: Schottky Diode;40V;1A/0.45V;PMDS;5.0*2.6*2.0mm;ROHS; Manufacture 1: Rohm; Geometry.Height: 2.0mm; Serial Number: 812600000141
D3 = DIODE-LED-BLUE-0603: LED;Blue;3V;LED-0603;0.5mm;ROHS; Manufacture 1 P/N: 19-217/BHC-ZL1M2RY/3T;BL-HB336G-TRB;HT-195NB5;; Manufacture 1: Everlight;佰鸿;Harvatek;; Serial Number: 81230000004
J1 J3 = DIP13X1-2.54: Geometry.Height: 0.05mm
J5 = MICRO-SIM-S0HG-180006-03G: 1.8H掀盖 Micro SIM卡座;16.3*14.66*1.8mm; Manufacture 1: 深圳市精睿兴业科技有限公司; Geometry.Height: 1.8mm
J7 = RF-ANT-SOCKET-U.FL-R-SMT: RF CONNECTOR;3*3*1.25mm;ROHS; Manufacture 1: Hirose; Serial Number: 80830000004; Geometry.Height: 1.25mm
JP1 = RESISTANCE: value: NI/0
K1 = KEY-2PIN: SWITCH-KEYPAD; Geometry.Height: 0.05mm; Value: 为射频留缺口 和KEYPAD-4.8X2.8X2.0不同之处
L4 L5 = BEAD-1000OHM-0402: Bead;1000ohm;250mA;0402;0.6mm;ROHS; Manufacture 1: Murata;Taiyo Yuden;Chilisin(奇力新)();; Manufacture 1 P/N: BLM15HD102SN1;BK1005HS102-T;SBJ100505T-102Y-N; Geometry.Height: 0.65mm; Serial Number: 80334000002
M2 = HOLE-0.9MM: Geometry.Height: 0.05mm
Q1 Q2 Q4 Q5 = TRIODE-NPN-MMBT3904: Transistor;NPN;40V;200mA;SOT23;1.1mm;ROHS; Manufacture 1: 长电; Serial Number: 81232000008
R1 = RES-20K-+/-5%-0402: RES FILM;20K;+/-5%;1/16W;0402;0.4mm;ROHS; Manufacture 1: YAGEO; Manufacture 1 P/N: RC0402JR-0720KL; Serial Number: 80114640009
R2 = RES-0-0402: RES FILM;0;1A;0402;0.4mm;ROHS; Manufacture 1: YAGEO; Manufacture 1 P/N: RC0402JR-070RL; Serial Number: 80114640001
R4 = RES-1K-0402: RES FILM;1K;+/-5%;1/16W;0402;0.4mm;ROHS; Manufacture 1 P/N: RC0402JR-071KL;WR04X102_JTL; Manufacture 1: YAGEO;Walsin; Geometry.Height: 0.40mm; Serial Number: 80114640003
R5 R14 = RES-4.7K-0402: RES FILM;4.7K;+/-5%;1/16W;0402;0.4mm;ROHS; Manufacture 1: YAGEO; Manufacture 1 P/N: RC0402JR-074K7L; Serial Number: 80114640017
R12 R46 = RES-10K-0402: RES FILM;10K;+/-5%;1/16W;0402;0.4mm;ROHS; Manufacture 1 P/N: RC0402JR-0710KL;WR04X103_JTL; Manufacture 1: YAGEO;Walsin; Serial Number: 80114640004
R15 = RES-10K-0402: RES FILM;10K;+/-5%;1/16W;0402;0.4mm;ROHS; Manufacture 1: YAGEO;Walsin; Manufacture 1 P/N: RC0402JR-0710KL;WR04X103_JTL; Serial Number: 80114640004
R23 = RES-100K-0402: RES FILM;100K;+/-5%;1/16W;0402;0.4mm;ROHS; Manufacture 1: YAGEO;Walsin; Manufacture 1 P/N: RC0402JR-07100KL;WR04X104_JTL;; Geometry.Height: 0.40mm; Serial Number: 80114640005
R29 = RES-47K-0402: RES FILM;47K;+/-5%;1/16W;0402;0.4mm;ROHS; Manufacture 1 P/N: RC0402JR-0747KL; Manufacture 1: YAGEO; Serial Number: 80114640048
R30 R33 R34 = RES-4.7K-0402: RES FILM;4.7K;+/-5%;1/16W;0402;0.4mm;ROHS; Manufacture 1 P/N: RC0402JR-074K7L; Manufacture 1: YAGEO; Serial Number: 80114640017
U2 = EM78P153B-SOP8: Manufacture: ELAN; Geometry.Height: 1.75mm
U3 = AIR202: Geometry.Height: 2.3 MM
VR1-VR8 = ESD-TVS-UM5079: TVS;7V;65pf;SOD882;ROHS; Manufacture 1: Union;韦尔;; Manufacture 1 P/N: ESD9X7V-2/TR;UM5079; Serial Number: 81121000008; Geometry.Height: 0.55mm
